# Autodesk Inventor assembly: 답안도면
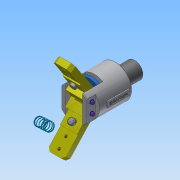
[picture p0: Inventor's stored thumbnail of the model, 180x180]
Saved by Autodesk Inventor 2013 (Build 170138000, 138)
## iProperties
Created: 2019-02
Part Number: 답안도면
Document SubType Name: Assembly
Designer: Administrator
Author: Administrator
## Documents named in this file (11)
- C:\Users\Administrator\Desktop\490207V1005\답안도면.iam
- C:\Users\Administrator\Desktop\490207V1005\본체.ipt
- C:\Users\Administrator\Desktop\490207V1005\E-링.ipt
- C:\Users\Administrator\Desktop\490207V1005\O-링.ipt
- C:\Users\Administrator\Desktop\490207V1005\가이드핀.ipt
- C:\Users\Administrator\Desktop\490207V1005\부시.ipt
- C:\Users\Administrator\Desktop\490207V1005\스프링.ipt
- C:\Users\Administrator\Desktop\490207V1005\평행핀 6x28.ipt
- C:\Users\Administrator\Desktop\490207V1005\피스톤.ipt
- C:\Users\Administrator\Desktop\490207V1005\핀.ipt
- C:\Users\Administrator\Desktop\490207V1005\핑거.ipt
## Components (11 placed, 6 different names)
1. E-링:1
2. O-링:1 — 각도:1, 각도:2
3. 가이드핀:1
4. 피스톤:1 — 플러쉬:3
5. 핀:1
6. 핑거:1 — 플러쉬:1
7. 핑거:2 — 플러쉬:2
8. O-링:2
9. 핀:2
10. E-링:2
11. 가이드핀:2
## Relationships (5: Flush 3, Angle 2)
- 각도:1 [Angle]: O-링:1
- 각도:2 [Angle]: O-링:1
- 플러쉬:1 [Flush]: 핑거:1
- 플러쉬:2 [Flush]: 핑거:2
- 플러쉬:3 [Flush]: 피스톤:1
